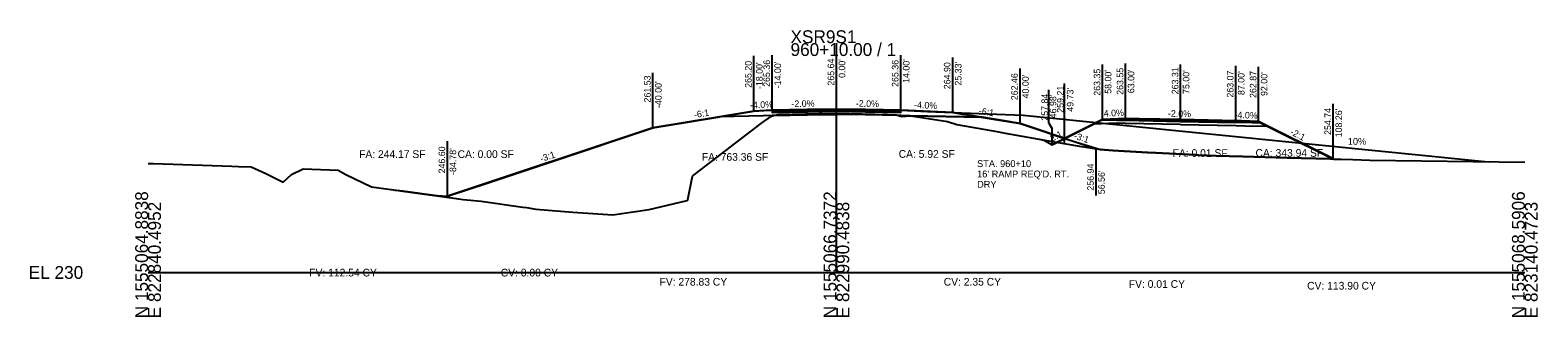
# Model space of a CAD drawing. Extents: x -26 to 823017, y -16 to 1558356.
# Drawn here: x -25.7 to 302.8, y 8990.3 to 9052.8 of the extents above; entities that cross this region are included whole.
import ezdxf

# ---------------------------------------------------------------- set-up
doc = ezdxf.new("R2010")
doc.units = 0
for name, color, linetype in [('ASPHALT_19MM1', 7, 'Continuous'), ('ASPHALT_9_5MM1', 7, 'Continuous'), ('CONST_DCH', 7, 'Continuous'), ('CONST_LV3', 7, 'Continuous'), ('Default', 7, 'Continuous'), ('Draft_XS_Grid', 7, 'Continuous'), ('DTM_CORRIDOR', 7, 'Continuous'), ('DTM_P_FINISHED_GRADE2', 7, 'Continuous'), ('DTM_TEMP_DROP', 7, 'Continuous'), ('DTM_X_GROUND', 7, 'Continuous'), ('PROFILES_DCH_2', 7, 'Continuous'), ('SLOPE_STAKES_FILL', 7, 'Continuous'), ('XS_CELL', 7, 'Continuous'), ('XS_M_SHAPES_EARTHWORK', 7, 'Continuous'), ('XS_P_ASPHALT', 7, 'Continuous'), ('XS_P_DR_GRAVEL', 7, 'Continuous'), ('XS_P_DRIVEWAY', 7, 'Continuous'), ('XS_P_GROUND', 7, 'Continuous'), ('XS_P_NULL_POINT', 7, 'Continuous'), ('XS_P_SHOULDER', 7, 'Continuous'), ('XS_P_SUBGRADE_GRANULAR', 7, 'Continuous'), ('XS_P_SUBGRADE_MILLING', 7, 'Continuous'), ('XS_P_SUBGRADE_UNDERCUT', 7, 'Continuous'), ('XS_P_TX_CLEARZONE', 7, 'Continuous'), ('XS_P_TX_FS_BS', 7, 'Continuous'), ('XS_SHEET_EW_TX_AREA', 7, 'Continuous'), ('XS_SHEET_EW_TX_VOLUME', 7, 'Continuous')]:
    doc.layers.add(name, color=color, linetype=linetype)

msp = doc.modelspace()

# ---------------------------------------------------------------- linework, layer by layer
at = {"layer": 'ASPHALT_19MM1'}
for points in [[(136, 9034.97), (136, 9034.86), (143.69, 9035.01), (150, 9035.14), (156.31, 9035.01), (164, 9034.86), (164, 9034.97), (164, 9035.07), (156.31, 9035.22), (150, 9035.35), (143.69, 9035.22), (136, 9035.07), (136, 9034.97)], [(213, 9033.17), (225, 9032.93), (237, 9032.69), (237, 9032.9), (225, 9033.14), (213, 9033.38), (213, 9033.17)]]:
    msp.add_lwpolyline(points, dxfattribs=at)
at = {"layer": 'ASPHALT_9_5MM1'}
msp.add_lwpolyline([(136, 9035.3), (136, 9035.23), (143.69, 9035.39), (150, 9035.51), (156.31, 9035.39), (164, 9035.23), (164, 9035.3), (164, 9035.36), (156.31, 9035.51), (150, 9035.64), (143.69, 9035.51), (136, 9035.36), (136, 9035.3)], dxfattribs=at)
at = {"layer": 'CONST_DCH'}
msp.add_lwpolyline([(213, 9033.38), (225, 9033.14), (237, 9032.9), (237, 9033.07), (225, 9033.31), (213, 9033.55), (213, 9033.38)], dxfattribs=at)
at = {"layer": 'CONST_LV3'}
for points in [[(150, 9035.64), (164, 9035.36)], [(175.33, 9034.9), (164, 9035.36)], [(110, 9031.53), (118.01, 9032.87), (124.59, 9033.96)], [(190, 9032.46), (186.59, 9033.03), (181.73, 9033.84)], [(196.98, 9027.84), (205.16, 9031.93), (208, 9033.35), (209.75, 9033.42), (213, 9033.55)], [(199.73, 9029.21), (201.63, 9030.17), (204.05, 9031.37), (205.16, 9031.93), (208, 9033.35), (209.75, 9033.42), (213, 9033.55), (217.21, 9033.46), (225, 9033.31), (229.21, 9033.22), (237, 9033.07), (240.25, 9032.94), (242, 9032.87), (247.54, 9030.1), (250.53, 9028.6), (251.3, 9028.22), (253.54, 9027.1), (253.62, 9027.06), (253.79, 9026.98), (254.87, 9026.44), (258.19, 9024.77), (258.38, 9024.73), (262.49, 9024.61), (266.25, 9024.51), (300, 9024.04)], [(242, 9032.87), (258.26, 9024.74)], [(164, 9026.68), (164, 9026.68), (164, 9026.68), (164, 9026.68), (164, 9026.68)], [(0, 9023.75), (1.2, 9023.77), (18.27, 9023.15), (19.73, 9023.12), (22.47, 9023.06), (25.64, 9021.58), (29.42, 9019.68), (31.29, 9021.33), (33.77, 9022.6), (41.4, 9022.27), (43.09, 9021.37), (48.67, 9018.68), (53.51, 9018), (53.75, 9017.97), (54.18, 9017.91), (55.48, 9017.74), (61.3, 9016.94), (63.02, 9016.7), (65.22, 9016.4)]]:
    msp.add_lwpolyline(points, dxfattribs=at)
at = {"layer": 'Default'}
msp.add_lwpolyline([(136, 9035.16), (136, 9035.07), (143.69, 9035.22), (150, 9035.35), (156.31, 9035.22), (164, 9035.07), (164, 9035.16), (164, 9035.23), (156.31, 9035.39), (150, 9035.51), (143.69, 9035.39), (136, 9035.23), (136, 9035.16)], dxfattribs=at)
at = {"layer": 'DTM_P_FINISHED_GRADE2'}
msp.add_lwpolyline([(65.22, 9016.6), (87.87, 9024.15), (110, 9031.53), (119.92, 9033.18), (132, 9035.2), (134.2, 9035.28), (136, 9035.36), (143.69, 9035.51), (150, 9035.64), (156.31, 9035.51), (164, 9035.36), (169.85, 9035.12), (175.33, 9034.9), (183.75, 9033.5), (190, 9032.46), (195.24, 9030.71), (199.73, 9029.21)], dxfattribs=at)
at = {"layer": 'DTM_X_GROUND'}
for points in [[(0, 9023.75), (1.2, 9023.77), (18.27, 9023.15), (19.73, 9023.12), (22.47, 9023.06), (25.64, 9021.58), (29.42, 9019.68), (31.29, 9021.33), (33.77, 9022.6), (41.4, 9022.27), (43.09, 9021.37), (48.67, 9018.68), (53.51, 9018), (53.75, 9017.97), (54.18, 9017.91), (55.48, 9017.76), (61.3, 9016.98), (63.02, 9016.81), (65.22, 9016.6), (74.12, 9019.57), (87.82, 9024.14), (87.87, 9024.15), (110, 9031.53), (119.92, 9033.18), (132, 9035.2), (134.2, 9035.28), (136, 9035.36), (143.69, 9035.51), (150, 9035.64), (156.31, 9035.51), (164, 9035.36), (169.85, 9035.12), (175.33, 9034.9), (183.75, 9033.5), (190, 9032.46), (195.24, 9030.71), (197.93, 9029.81), (199.73, 9029.21), (201.63, 9030.17), (204.05, 9031.37), (205.16, 9031.93), (208, 9033.35), (209.75, 9033.42), (213, 9033.55), (217.21, 9033.46), (225, 9033.31), (229.21, 9033.22), (237, 9033.07), (240.25, 9032.94), (242, 9032.87), (247.54, 9030.1), (250.53, 9028.6), (251.3, 9028.22), (253.54, 9027.1), (253.62, 9027.06), (253.79, 9026.98), (254.87, 9026.44), (258.19, 9024.77), (258.38, 9024.73), (262.49, 9024.61), (266.25, 9024.51), (300, 9024.04)], [(0, 9023.75), (1.2, 9023.77), (18.27, 9023.15), (19.73, 9023.12), (22.47, 9023.06), (25.64, 9021.58), (29.42, 9019.68), (31.29, 9021.33), (33.77, 9022.6), (41.4, 9022.27), (43.09, 9021.37), (48.67, 9018.68), (53.51, 9018), (55.48, 9017.74), (63.02, 9016.7), (68.65, 9015.94), (72.55, 9015.56), (81.64, 9014.22), (82.45, 9014.13), (84.47, 9013.8), (92.55, 9013.12), (101.26, 9012.58), (103.24, 9012.86), (109.22, 9013.7), (117.45, 9015.71), (117.59, 9015.9), (118.62, 9021), (118.68, 9021.06), (118.78, 9021.15), (118.98, 9021.29), (120.3, 9022.29), (133.7, 9032.55), (135.83, 9034.07), (136.31, 9034.2), (137.31, 9034.45), (146.29, 9034.63), (150.18, 9034.71), (161.13, 9034.44), (162.82, 9034.4), (163.01, 9034.34), (164.24, 9033.99), (166.1, 9034.13), (166.2, 9034.13), (174.21, 9032.91), (176.25, 9032.28), (184.92, 9030.7), (186.79, 9030.38), (194.15, 9029.05), (197.48, 9028.49), (202.97, 9027.51), (207.51, 9026.79), (210.24, 9026.59), (217.72, 9026.19), (219.57, 9026.06), (228.33, 9025.62), (228.88, 9025.59), (232.73, 9025.41), (238.55, 9025.25), (248.24, 9025), (257.62, 9024.76), (262.49, 9024.61), (266.25, 9024.51), (300, 9024.04)], [(0, 9023.75), (1.2, 9023.77), (18.27, 9023.15), (19.73, 9023.12), (22.47, 9023.06), (25.64, 9021.58), (29.42, 9019.68), (31.29, 9021.33), (33.77, 9022.6), (41.4, 9022.27), (43.09, 9021.37), (48.67, 9018.68), (53.51, 9018), (55.48, 9017.74), (63.02, 9016.7), (68.65, 9015.94), (72.55, 9015.56), (81.64, 9014.22), (82.45, 9014.13), (84.47, 9013.8), (92.55, 9013.12), (101.26, 9012.58), (103.24, 9012.86), (109.22, 9013.7), (117.45, 9015.71), (117.59, 9015.9), (118.62, 9021), (118.68, 9021.06), (118.78, 9021.15), (118.98, 9021.29), (120.3, 9022.29), (133.7, 9032.55), (135.83, 9034.07), (136.31, 9034.2), (137.31, 9034.45), (146.29, 9034.63), (150.18, 9034.71), (161.13, 9034.44), (162.82, 9034.4), (163.01, 9034.34), (164.24, 9033.99), (166.1, 9034.13), (166.2, 9034.13), (174.21, 9032.91), (176.25, 9032.28), (184.92, 9030.7), (186.79, 9030.38), (194.15, 9029.05), (195.21, 9028.87), (196.98, 9027.84), (197.96, 9028.33), (201.63, 9030.17), (205.16, 9031.93), (208, 9033.35), (209.75, 9033.42), (213, 9033.55), (217.21, 9033.46), (225, 9033.31), (229.21, 9033.22), (237, 9033.07), (240.25, 9032.94), (242, 9032.87), (247.54, 9030.1), (250.53, 9028.6), (251.3, 9028.22), (253.54, 9027.1), (253.62, 9027.06), (253.79, 9026.98), (254.87, 9026.44), (258.19, 9024.77), (258.38, 9024.73), (262.49, 9024.61), (266.25, 9024.51), (300, 9024.04)]]:
    msp.add_lwpolyline(points, dxfattribs=at)
at = {"layer": 'XS_CELL'}
for p, q in [((150, 9000), (150, 9050)), ((0, 9000), (150, 9000)), ((150, 9000), (300, 9000))]:
    msp.add_line(p, q, dxfattribs=at)
at = {"layer": 'XS_M_SHAPES_EARTHWORK'}
for points in [[(136.3, 9034.2), (136.31, 9034.2), (137.31, 9034.45), (146.29, 9034.63), (150.18, 9034.71), (161.13, 9034.44), (162.82, 9034.4), (163.01, 9034.34), (163.49, 9034.2), (156.31, 9034.34), (150, 9034.47), (143.69, 9034.34)], [(65.22, 9016.6), (65.22, 9016.4), (68.65, 9015.94), (72.55, 9015.56), (81.64, 9014.22), (82.45, 9014.13), (84.47, 9013.8), (92.55, 9013.12), (101.26, 9012.58), (103.24, 9012.86), (109.22, 9013.7), (117.45, 9015.71), (117.59, 9015.9), (118.62, 9021), (118.68, 9021.06), (118.78, 9021.15), (118.98, 9021.29), (120.3, 9022.29), (133.7, 9032.55), (135.83, 9034.07), (136.3, 9034.2), (136, 9034.19), (134, 9034.15), (124.59, 9033.96), (118.01, 9032.87), (110, 9031.53)], [(163.49, 9034.2), (164.24, 9033.99), (166.1, 9034.13), (166.2, 9034.13), (174.21, 9032.91), (176.25, 9032.28), (184.92, 9030.7), (186.79, 9030.38), (194.15, 9029.05), (197.48, 9028.49), (199.73, 9028.09), (199.73, 9029.21), (195.24, 9030.71), (190, 9032.46), (183.75, 9033.5), (181.73, 9033.84), (166, 9034.15), (164, 9034.19)]]:
    msp.add_lwpolyline(points, close=True, dxfattribs=at)
at = {"layer": 'XS_P_DR_GRAVEL'}
for points in [[(209.75, 9033.42), (208, 9033.35), (207.91, 9033.3), (207.86, 9033.28), (211.2, 9033.21), (213, 9033.17), (213, 9033.31), (213, 9033.55), (209.75, 9033.42)], [(240.25, 9032.94), (242, 9032.87), (242.37, 9032.68), (242.57, 9032.58), (240.62, 9032.62), (237, 9032.69), (237, 9032.83), (237, 9033.07), (240.25, 9032.94)]]:
    msp.add_lwpolyline(points, dxfattribs=at)
at = {"layer": 'XS_P_DRIVEWAY'}
for p, q in [((175.33, 9034.9), (190.67, 9034.29)), ((190.67, 9034.29), (292.04, 9024.15))]:
    msp.add_line(p, q, dxfattribs=at)
msp.add_lwpolyline([(136, 9034.19), (134, 9034.15), (124.59, 9033.96)], dxfattribs=at)
at = {"layer": 'XS_P_GROUND'}
for points in [[(132, 9035.2), (110, 9031.53), (65.22, 9016.6)], [(199.73, 9029.21), (195.24, 9030.71), (190, 9032.46), (183.75, 9033.5), (175.33, 9034.9)], [(175.33, 9034.9), (190, 9032.46), (206.56, 9026.94), (206.56, 9026.94)], [(208, 9033.35), (196.98, 9027.84)], [(242, 9032.87), (258.19, 9024.77)], [(258.26, 9024.74), (257.62, 9024.76), (248.24, 9025), (238.55, 9025.25), (232.73, 9025.41), (228.88, 9025.59), (228.33, 9025.62), (219.57, 9026.06), (217.72, 9026.19), (210.24, 9026.59), (207.51, 9026.79), (206.56, 9026.94)], [(258.26, 9024.74), (257.62, 9024.76), (248.24, 9025), (238.55, 9025.25), (232.73, 9025.41), (228.88, 9025.59), (228.33, 9025.62), (219.57, 9026.06), (217.72, 9026.19), (210.24, 9026.59), (207.51, 9026.79), (206.56, 9026.94)]]:
    msp.add_lwpolyline(points, dxfattribs=at)
at = {"layer": 'XS_P_SHOULDER'}
for points in [[(136, 9035.36), (132, 9035.2)], [(164, 9035.36), (175.33, 9034.9)], [(208, 9033.35), (209.75, 9033.42), (213, 9033.55)], [(242, 9032.87), (240.25, 9032.94), (237, 9033.07)]]:
    msp.add_lwpolyline(points, dxfattribs=at)
at = {"layer": 'XS_P_SUBGRADE_GRANULAR'}
for points in [[(136, 9034.19), (143.69, 9034.34), (150, 9034.47)], [(164, 9034.19), (156.31, 9034.34), (150, 9034.47)], [(164, 9034.19), (166, 9034.15), (181.73, 9033.84)], [(213, 9032.51), (211, 9032.55), (206, 9032.35)], [(225, 9032.27), (213, 9032.51)], [(225, 9032.27), (237, 9032.03)], [(237, 9032.03), (239, 9031.99), (243.96, 9031.89)]]:
    msp.add_lwpolyline(points, dxfattribs=at)
at = {"layer": 'XS_P_SUBGRADE_UNDERCUT'}
msp.add_lwpolyline([(207.51, 9026.79), (230.8, 9025.5), (244.61, 9025.12), (258.29, 9024.75), (242, 9032.88), (238.25, 9033.03), (234.01, 9033.14), (225, 9033.32), (215.99, 9033.5), (213, 9033.56), (208, 9033.36), (199.73, 9029.21)], close=True, dxfattribs=at)
at = {"layer": 'XS_P_TX_CLEARZONE'}
for p, q in [((132, 9035.2), (132, 9047.2)), ((136, 9035.36), (136, 9047.36)), ((150, 9035.64), (150, 9047.64)), ((164, 9035.36), (164, 9047.36)), ((175.33, 9034.9), (175.33, 9046.9)), ((208, 9033.35), (208, 9045.35)), ((213, 9033.55), (213, 9045.55)), ((225, 9033.31), (225, 9045.31)), ((237, 9033.07), (237, 9045.07)), ((242, 9032.87), (242, 9044.87)), ((110, 9031.53), (110, 9043.53)), ((190, 9032.46), (190, 9044.46)), ((190, 9032.46), (190, 9044.46)), ((196.27, 9032.54), (196.27, 9039.84)), ((199.73, 9029.21), (199.73, 9041.21)), ((258.26, 9024.74), (258.26, 9036.74)), ((196.27, 9032.54), (196.98, 9031.33)), ((65.22, 9016.6), (65.22, 9028.6)), ((196.98, 9027.84), (196.98, 9031.33)), ((206.56, 9016.81), (206.56, 9026.94))]:
    msp.add_line(p, q, dxfattribs=at)

# ---------------------------------------------------------------- texts
at = {"layer": 'CONST_DCH'}
for p in [(196.9, 9027.72), (258.11, 9024.65), (258.18, 9024.62)]:
    msp.add_text('X', height=0.24, dxfattribs=at).set_placement(p)
at = {"layer": 'Draft_XS_Grid'}
msp.add_text('-', height=0.0001, dxfattribs=at).set_placement((0, 9000))
at = {"layer": 'DTM_CORRIDOR'}
for p in [(212.92, 9033.43), (224.92, 9033.19), (236.92, 9032.95)]:
    msp.add_text('X', height=0.24, dxfattribs=at).set_placement(p)
at = {"layer": 'DTM_TEMP_DROP'}
for p in [(135.92, 9035.24), (149.92, 9035.52), (163.92, 9035.24)]:
    msp.add_text('X', height=0.24, dxfattribs=at).set_placement(p)
at = {"layer": 'PROFILES_DCH_2'}
for p in [(175.25, 9034.78), (189.92, 9032.34), (206.48, 9026.82), (258.18, 9024.62)]:
    msp.add_text('X', height=0.24, dxfattribs=at).set_placement(p)
at = {"layer": 'SLOPE_STAKES_FILL'}
for p in [(199.65, 9029.09), (65.14, 9016.48)]:
    msp.add_text('X', height=0.24, dxfattribs=at).set_placement(p)
at = {"layer": 'XS_CELL'}
for s, p in [('XSR9S1', (140, 9050)), ('960+10.00 / 1', (140, 9047.2)), ('EL 230', (-26, 8998.6))]:
    msp.add_text(s, height=2.8, dxfattribs=at).set_placement(p)
for s, p in [('N 1555064.8838', (0, 8990)), ('E 822840.4952', (2.8, 8990)), ('N 1555066.7372', (150, 8990)), ('E 822990.4838', (152.8, 8990)), ('N 1555068.5906', (300, 8990)), ('E 823140.4723', (302.8, 8990))]:
    msp.add_text(s, height=2.8, rotation=90, dxfattribs=at).set_placement(p)
at = {"layer": 'XS_P_ASPHALT'}
for p in [(196.9, 9027.72), (258.11, 9024.65)]:
    msp.add_text('X', height=0.24, dxfattribs=at).set_placement(p)
at = {"layer": 'XS_P_DRIVEWAY'}
for s, p in [('10%', (261.43, 9027.83)), ('STA. 960+10', (180.65, 9022.97)), ("16' RAMP REQ'D. RT.", (180.65, 9020.72)), ('DRY', (180.65, 9018.47))]:
    msp.add_text(s, height=1.5, dxfattribs=at).set_placement(p)
at = {"layer": 'XS_P_NULL_POINT'}
for p in [(199.65, 9029.09), (65.14, 9016.48)]:
    msp.add_text('X', height=0.24, dxfattribs=at).set_placement(p)
at = {"layer": 'XS_P_SHOULDER'}
for p in [(109.92, 9031.41), (189.92, 9032.34), (207.92, 9033.23), (241.92, 9032.75)]:
    msp.add_text('X', height=0.24, dxfattribs=at).set_placement(p)
at = {"layer": 'XS_P_SUBGRADE_MILLING'}
for p in [(131.92, 9035.08), (175.25, 9034.78)]:
    msp.add_text('X', height=0.24, dxfattribs=at).set_placement(p)
at = {"layer": 'XS_P_TX_CLEARZONE'}
for s, p in [('265.20', (131.52, 9040.25)), ("-18.00'", (133.92, 9039.99)), ('265.36', (135.52, 9040.46)), ("-14.00'", (137.92, 9040.15)), ('265.64', (149.52, 9040.75)), ("0.00'", (151.92, 9042.42)), ('265.36', (163.52, 9040.46)), ("14.00'", (165.92, 9041.33)), ('264.90', (174.85, 9039.96)), ("25.33'", (177.25, 9040.74)), ('263.55', (212.52, 9038.73)), ('263.31', (224.52, 9038.85)), ('261.53', (109.52, 9037.07)), ("-40.00'", (111.92, 9035.85)), ('262.46', (189.52, 9037.56)), ("40.00'", (191.92, 9037.95)), ('263.35', (207.52, 9038.53)), ("58.00'", (209.92, 9038.96)), ("63.00'", (214.92, 9039.09)), ("75.00'", (226.92, 9038.92)), ('263.07', (236.52, 9038.13)), ("87.00'", (238.92, 9038.68)), ('262.87', (241.52, 9038.05)), ("92.00'", (243.92, 9038.48)), ('257.84', (196.11, 9033.08)), ("46.98'", (197.92, 9033.61)), ('259.21', (199.51, 9034.82)), ("49.73'", (201.65, 9035.05)), ('254.74', (257.78, 9029.98)), ("108.26'", (260.18, 9029.46)), ('246.60', (64.74, 9021.59)), ("-84.78'", (67.14, 9021.26)), ('256.94', (206.08, 9017.84)), ("56.56'", (208.48, 9017.06))]:
    msp.add_text(s, height=1.44, rotation=90, dxfattribs=at).set_placement(p)
at = {"layer": 'XS_P_TX_FS_BS'}
for s, rotation, p in [('-6:1', 9.4642, (119.08, 9033.65)), ('-4.0%', 2.2906, (131.18, 9035.76)), ('-2.0%', 1.1458, (140.2, 9036.04)), ('-2.0%', 358.8542, (154.22, 9036.15)), ('-4.0%', 357.7094, (166.9, 9035.84)), ('-6:1', 350.5358, (180.94, 9034.58)), ('4.0%', 2.2906, (208.27, 9033.96)), ('-2.0%', 358.8542, (222.22, 9033.96)), ('-4.0%', 357.7094, (236.73, 9033.68)), ('2:1', 26.5672, (196.99, 9028.52)), ('-3:1', 341.5663, (201.61, 9029.22)), ('-2:1', 333.4349, (248.74, 9030.17)), ('-3:1', 18.4332, (85.7, 9024.06))]:
    msp.add_text(s, height=1.44, rotation=rotation, dxfattribs=at).set_placement(p)
at = {"layer": 'XS_SHEET_EW_TX_AREA'}
for s, p in [('FA: 244.17 SF', (45.98, 9024.96)), ('CA: 0.00 SF', (67.45, 9024.96)), ('FA: 763.36 SF', (120.66, 9024.35)), ('CA: 5.92 SF', (163.56, 9025)), ('FA: 0.01 SF', (223.26, 9025.2)), ('CA: 343.94 SF', (241.32, 9025.22))]:
    msp.add_text(s, height=1.68, dxfattribs=at).set_placement(p)
at = {"layer": 'XS_SHEET_EW_TX_VOLUME'}
for s, p in [('FV: 112.54 CY', (35.12, 8999.12)), ('CV: 0.00 CY', (76.85, 8999.12)), ('FV: 278.83 CY', (111.45, 8997.12)), ('CV: 2.35 CY', (173.38, 8997.12)), ('FV: 0.01 CY', (213.71, 8996.63)), ('CV: 113.90 CY', (252.57, 8996.26))]:
    msp.add_text(s, height=1.68, dxfattribs=at).set_placement(p)

doc.saveas('drawing.dxf')
